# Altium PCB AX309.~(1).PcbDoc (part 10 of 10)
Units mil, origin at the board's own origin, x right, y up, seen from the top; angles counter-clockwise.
Board outline 5185 x 3614 mil, 4 copper layers (Top Layer, GND, Mid-Layer 1, Bottom Layer); 191 components, 352 nets, 1106 pads, 425 vias.
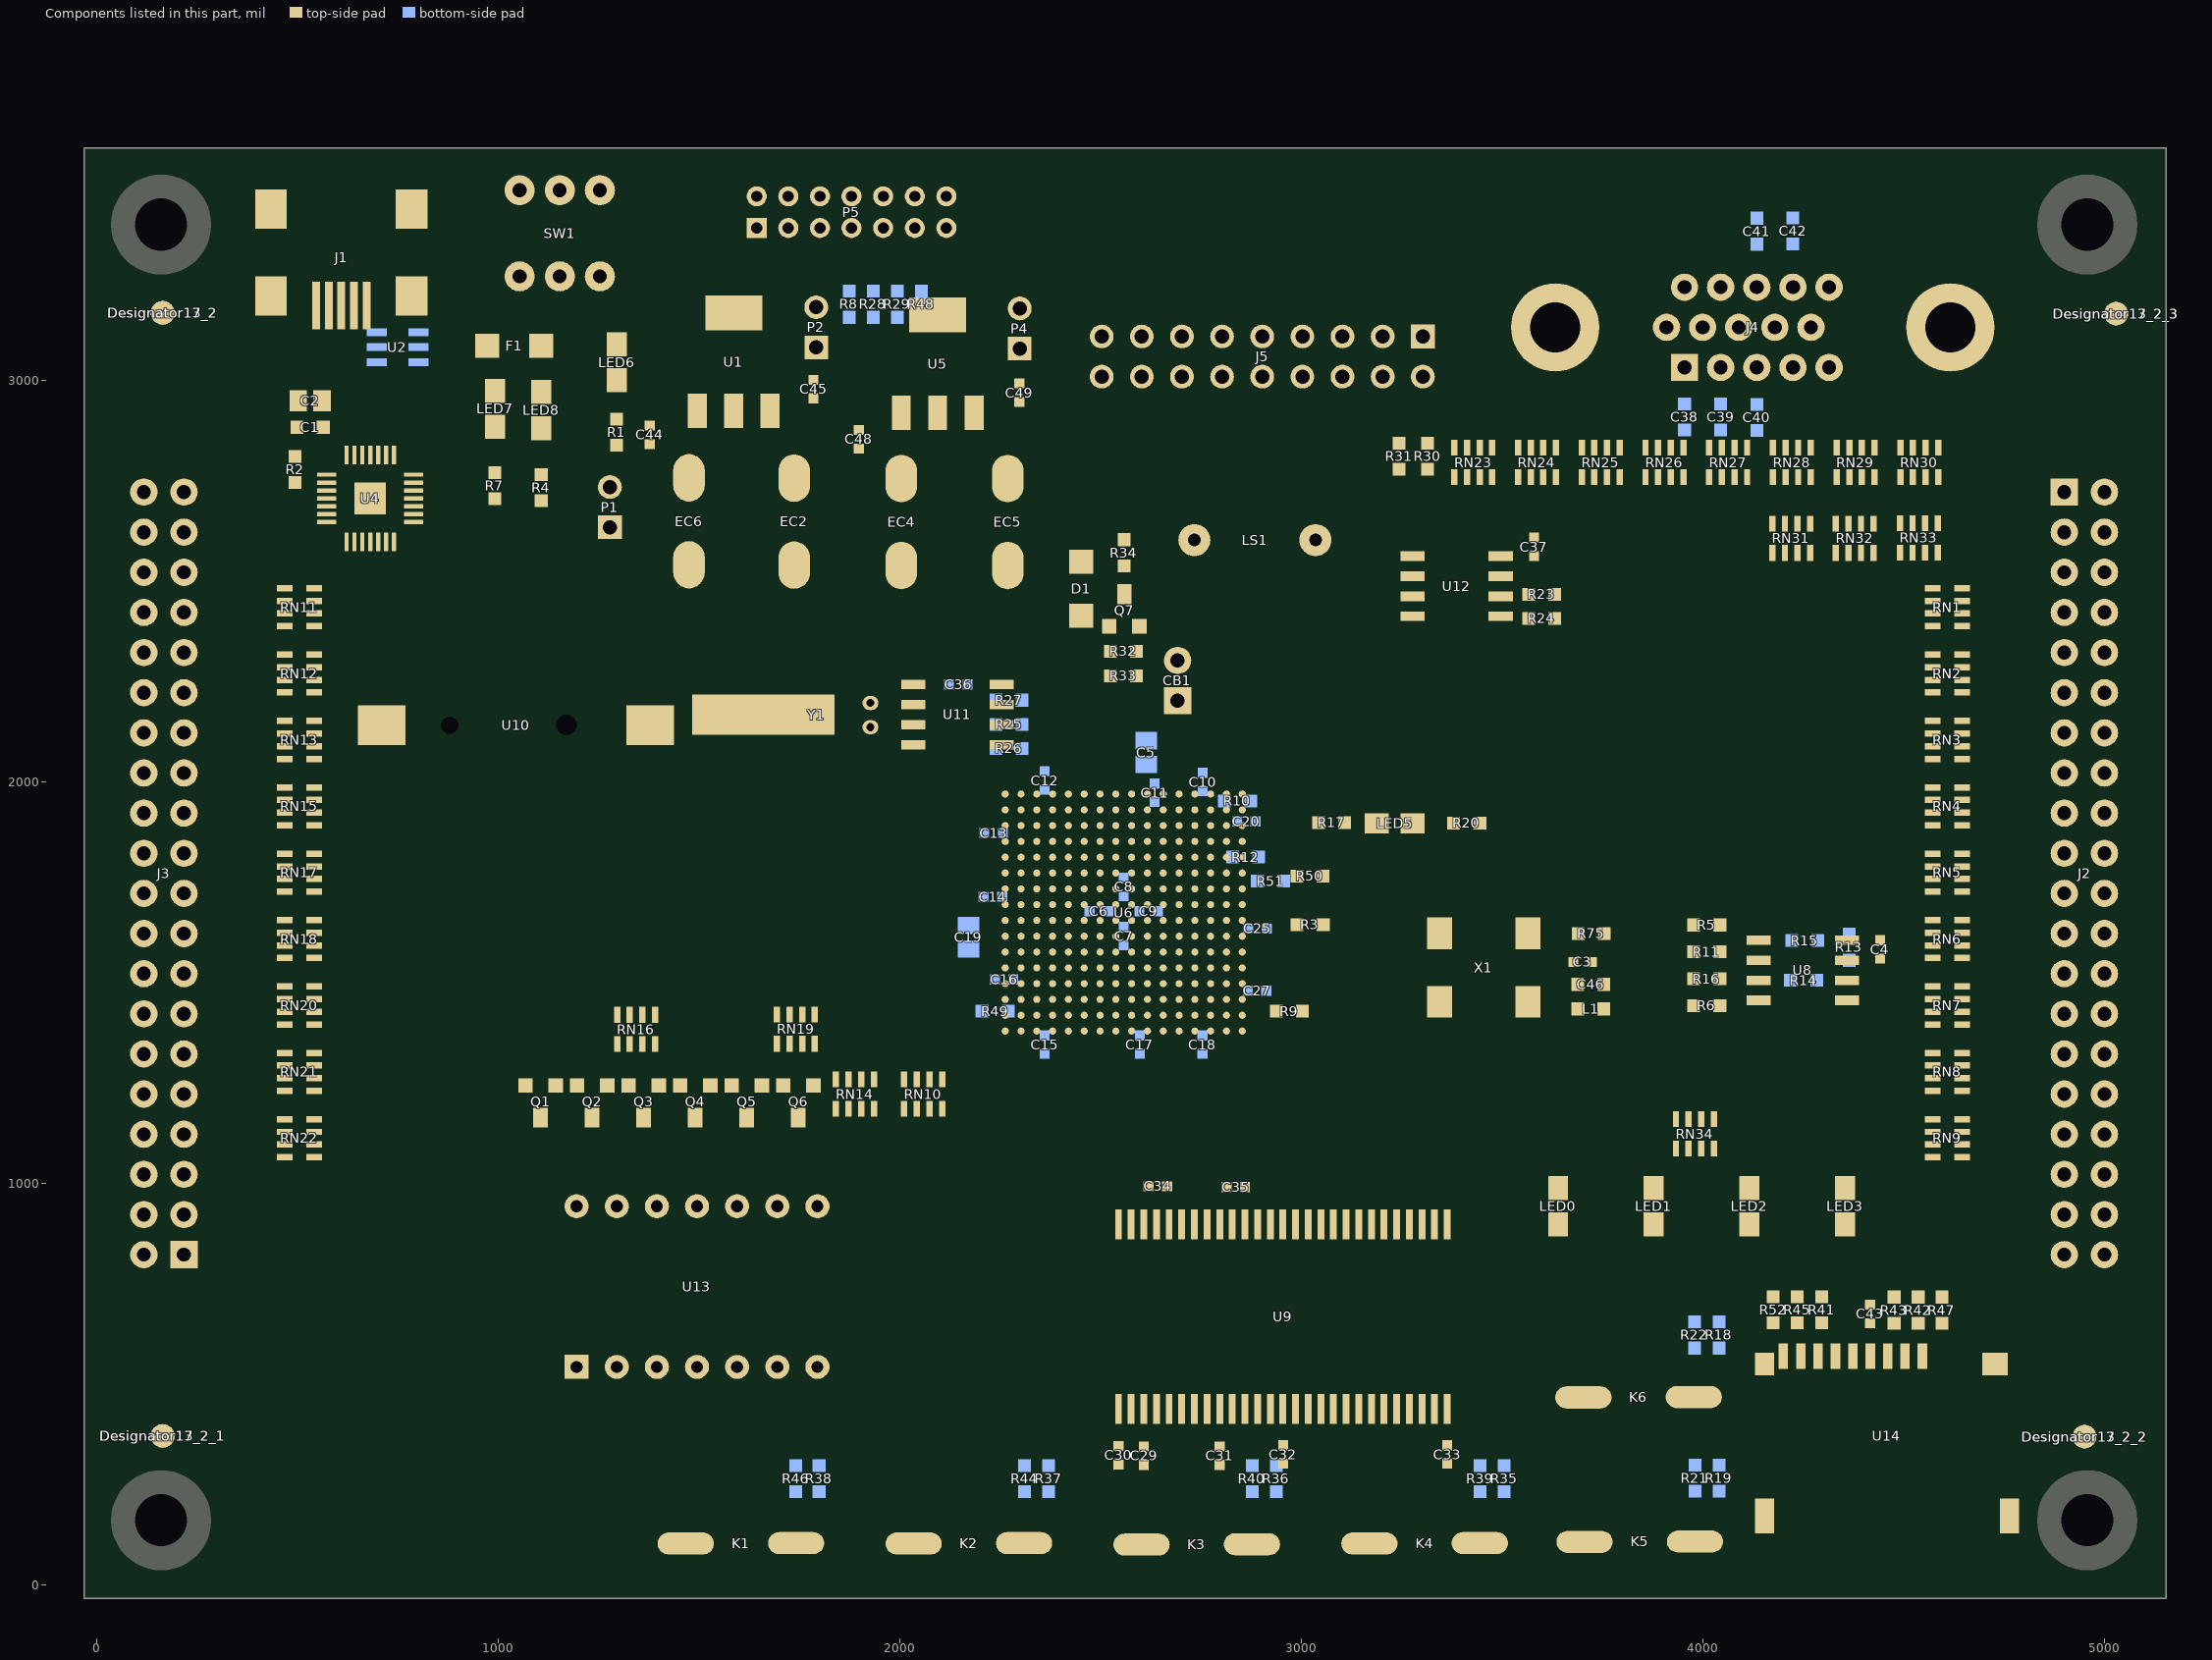
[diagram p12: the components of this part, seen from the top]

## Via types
v1: diameter 20, hole 10, Top Layer to Bottom Layer, 328 vias
v2: diameter 30, hole 15, Top Layer to Bottom Layer, 95 vias
v3: diameter 40, hole 20, Top Layer to Bottom Layer, 2 vias

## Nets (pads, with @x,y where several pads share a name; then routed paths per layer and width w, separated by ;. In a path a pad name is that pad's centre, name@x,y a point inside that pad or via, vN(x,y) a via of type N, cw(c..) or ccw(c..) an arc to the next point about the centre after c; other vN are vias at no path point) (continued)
copper on no net: (continued)
  Top Layer w0.7: 1160.7,143.2 1182.63,143.2 ; 1160.7,183.1 1200.13,183.1 ; 1160.7,183.8 1200.83,183.8 ; 1161.4,143.9 1181.93,143.9 ; 1161.4,181.7 1198.73,181.7 ; 1161.4,182.4 1199.43,182.4 ; 1162.1,144.6 1181.93,144.6 ; 1162.1,180.3 1197.33,180.3 ; 1162.1,181 1198.03,181 ; 1162.8,145.3 1181.23,145.3 ; 1162.8,179.6 1196.63,179.6 ; 1163.5,146 1181.23,146 ; 1163.5,178.2 1195.23,178.2 ; 1163.5,178.9 1195.93,178.9 ; 1164.2,146.7 1180.53,146.7 ; 1164.2,176.8 1193.83,176.8 ; 1164.2,177.5 1194.53,177.5 ; 1164.9,147.4 1180.53,147.4 ; 1164.9,175.4 1192.43,175.4 ; 1164.9,176.1 1193.13,176.1 ; 1165.6,148.1 1179.83,148.1 ; 1165.6,174.7 1191.73,174.7 ; 1166.3,148.8 1179.83,148.8 ; 1166.3,149.5 1179.13,149.5 ; 1166.3,173.3 1190.33,173.3 ; 1166.3,174 1191.03,174 ; 1167,150.2 1179.13,150.2 ; 1167,171.9 1188.93,171.9 ; 1167,172.6 1189.63,172.6 ; 1167.7,150.9 1178.43,150.9 ; 1167.7,170.5 1187.53,170.5 ; 1167.7,171.2 1188.23,171.2 ; 1168.4,151.6 1178.43,151.6 ; 1168.4,169.8 1186.83,169.8 ; 1169.1,152.3 1177.73,152.3 ; 1169.1,168.4 1185.43,168.4 ; 1169.1,169.1 1186.13,169.1 ; 1169.8,153 1177.03,153 ; 1169.8,167 1184.03,167 ; 1169.8,167.7 1184.73,167.7 ; 1170.5,153.7 1177.03,153.7 ; 1170.5,165.6 1182.63,165.6 ; 1170.5,166.3 1183.33,166.3 ; 1171.2,154.4 1176.33,154.4 ; 1171.2,164.9 1181.93,164.9 ; 1171.9,155.1 1176.33,155.1 ; 1171.9,163.5 1180.53,163.5 ; 1171.9,164.2 1181.23,164.2 ; 1172.6,155.8 1175.63,155.8 ; 1172.6,162.1 1179.13,162.1 ; 1172.6,162.8 1179.83,162.8 ; 1173.3,156.5 1175.63,156.5 ; 1173.3,160.7 1177.73,160.7 ; 1173.3,161.4 1178.43,161.4 ; 1174,157.2 1174.93,157.2 ; 1174,157.9 1174.93,157.9 ; 1174,159.3 1176.33,159.3 ; 1174,160 1177.03,160 ; 1174.7,158.6 1175.63,158.6 ; 1190.8,157.9 1259.63,157.9 ; 1191.5,156.5 1258.23,156.5 ; 1191.5,157.2 1258.93,157.2 ; 1191.5,158.6 1260.33,158.6 ; 1192.2,155.1 1257.53,155.1 ; 1192.2,155.8 1257.53,155.8 ; 1192.2,159.3 1261.03,159.3 ; 1192.9,153.7 1256.13,153.7 ; 1192.9,154.4 1256.83,154.4 ; 1192.9,160 1261.73,160 ; 1193.6,152.3 1254.73,152.3 ; 1193.6,153 1255.43,153 ; 1193.6,160.7 1262.43,160.7 ; 1194.3,150.9 1253.33,150.9 ; 1194.3,151.6 1254.03,151.6 ; 1194.3,161.4 1263.13,161.4 ; 1195,149.5 1253.33,149.5 ; 1195,150.2 1252.63,150.2 ; 1195,162.1 1263.83,162.1 ; 1195.7,148.8 1253.33,148.8 ; 1195.7,162.8 1264.53,162.8 ; 1196.4,147.4 1254.03,147.4 ; 1196.4,148.1 1254.03,148.1 ; 1196.4,163.5 1265.23,163.5 ; 1197.1,146 1254.73,146 ; 1197.1,146.7 1254.73,146.7 ; 1197.1,164.2 1265.93,164.2 ; 1197.8,144.6 1255.43,144.6 ; 1197.8,145.3 1255.43,145.3 ; 1197.8,164.9 1265.93,164.9 ; 1198.5,143.2 1256.13,143.2 ; 1198.5,143.9 1256.13,143.9 ; 1198.5,165.6 1266.63,165.6 ; 1199.2,141.8 1257.53,141.8 ; 1199.2,142.5 1256.83,142.5 ; 1199.2,166.3 1267.33,166.3 ; 1199.9,140.4 1258.23,140.4 ; 1199.9,141.1 1257.53,141.1 ; 1199.9,167 1268.03,167 ; 1200.6,139 1258.93,139 ; 1200.6,139.7 1258.23,139.7 ; 1200.6,167.7 1268.73,167.7 ; 1201.3,137.6 1259.63,137.6 ; 1201.3,138.3 1258.93,138.3 ; 1201.3,168.4 1269.43,168.4 ; 1202,136.2 1260.33,136.2 ; 1202,136.9 1259.63,136.9 ; 1202,169.1 1270.13,169.1 ; 1202.7,135.5 1260.33,135.5 ; 1202.7,169.8 1270.83,169.8 ; 1203.4,134.1 1261.03,134.1 ; 1203.4,134.8 1261.03,134.8 ; 1203.4,170.5 1271.53,170.5 ; 1204.1,132.7 1261.73,132.7 ; 1204.1,133.4 1261.73,133.4 ; 1204.1,171.2 1272.23,171.2 ; 1204.8,131.3 1263.13,131.3 ; 1204.8,132 1262.43,132 ; 1204.8,171.9 1272.93,171.9 ; 1205.5,129.9 1263.83,129.9 ; 1205.5,130.6 1263.13,130.6 ; 1205.5,172.6 1273.63,172.6 ; 1206.2,128.5 1264.53,128.5 ; 1206.2,129.2 1263.83,129.2 ; 1206.2,173.3 1274.33,173.3 ; 1206.9,127.1 1265.23,127.1 ; 1206.9,127.8 1264.53,127.8 ; 1206.9,174 1274.33,174 ; 1207.6,125.7 1265.93,125.7 ; 1207.6,126.4 1265.23,126.4 ; 1207.6,174.7 1275.03,174.7 ; 1208.3,124.3 1266.63,124.3 ; 1208.3,125 1265.93,125 ; 1208.3,175.4 1275.73,175.4 ; 1209,122.9 1267.33,122.9 ; 1209,123.6 1266.63,123.6 ; 1209,176.1 1276.43,176.1 ; 1209.7,122.2 1267.33,122.2 ; 1209.7,176.8 1277.13,176.8 ; 1210.4,120.8 1268.73,120.8 ; 1210.4,121.5 1268.03,121.5 ; 1210.4,177.5 1277.83,177.5 ; 1211.1,119.4 1269.43,119.4 ; 1211.1,120.1 1268.73,120.1 ; 1211.1,178.2 1278.53,178.2 ; 1211.8,118 1270.13,118 ; 1211.8,118.7 1269.43,118.7 ; 1211.8,178.9 1279.23,178.9 ; 1212.5,116.6 1270.83,116.6 ; 1212.5,117.3 1270.13,117.3 ; 1212.5,179.6 1279.93,179.6 ; 1213.2,115.2 1271.53,115.2 ; 1213.2,115.9 1270.83,115.9 ; 1213.2,180.3 1280.63,180.3 ; 1213.9,113.8 1272.23,113.8 ; 1213.9,114.5 1271.53,114.5 ; 1213.9,181 1281.33,181 ; 1214.6,112.4 1272.93,112.4 ; 1214.6,113.1 1272.23,113.1 ; 1214.6,181.7 1282.03,181.7 ; 1215.3,111.7 1273.63,111.7 ; 1215.3,182.4 1282.73,182.4 ; 1216,110.3 1274.33,110.3 ; 1216,111 1273.63,111 ; 1216,183.1 1282.73,183.1 ; 1216.7,108.9 1275.03,108.9 ; 1216.7,109.6 1274.33,109.6 ; 1216.7,183.8 1283.43,183.8 ; 1217.4,107.5 1275.73,107.5 ; 1217.4,108.2 1275.03,108.2 ; 1217.4,184.5 1284.13,184.5 ; 1218.1,106.8 1275.73,106.8 ; 1218.1,185.2 1284.83,185.2 ; 1218.8,105.4 1276.43,105.4 ; 1218.8,106.1 1276.43,106.1 ; 1218.8,185.9 1285.53,185.9 ; 1219.5,104 1277.13,104 ; 1219.5,104.7 1277.13,104.7 ; 1219.5,186.6 1286.23,186.6 ; 1220.2,102.6 1277.83,102.6 ; 1220.2,103.3 1277.83,103.3 ; 1220.2,187.3 1286.93,187.3 ; 1220.9,101.2 1279.23,101.2 ; 1220.9,101.9 1278.53,101.9 ; 1220.9,188 1287.63,188 ; 1221.6,99.8 1279.93,99.8 ; 1221.6,100.5 1279.23,100.5 ; 1221.6,188.7 1288.33,188.7 ; 1222.3,98.4 1280.63,98.4 ; 1222.3,99.1 1279.93,99.1 ; 1222.3,189.4 1289.03,189.4 ; 1223,97 1281.33,97 ; 1223,97.7 1280.63,97.7 ; 1223,190.1 1289.73,190.1 ; 1223.7,95.6 1282.03,95.6 ; 1223.7,96.3 1281.33,96.3 ; 1223.7,190.8 1290.43,190.8 ; 1224.4,94.2 1282.73,94.2 ; 1224.4,94.9 1282.03,94.9 ; 1224.4,191.5 1291.13,191.5 ; 1225.1,92.8 1283.43,92.8 ; 1225.1,93.5 1282.73,93.5 ; 1225.1,192.2 1291.83,192.2 ; 1225.8,91.4 1284.13,91.4 ; 1225.8,92.1 1284.13,92.1 ; 1225.8,192.9 1291.83,192.9 ; 1226.5,90 1284.83,90 ; 1226.5,90.7 1284.83,90.7 ; 1226.5,193.6 1292.53,193.6 ; 1227.2,89.3 1285.53,89.3 ; 1227.2,194.3 1293.23,194.3 ; 1227.9,87.9 1286.23,87.9 ; 1227.9,88.6 1285.53,88.6 ; 1227.9,195 1293.93,195 ; 1228.6,86.5 1286.93,86.5 ; 1228.6,87.2 1286.23,87.2 ; 1228.6,195.7 1294.63,195.7 ; 1229.3,85.1 1287.63,85.1 ; 1229.3,85.8 1286.93,85.8 ; 1229.3,196.4 1295.33,196.4 ; 1230,83.7 1288.33,83.7 ; 1230,84.4 1287.63,84.4 ; 1230,197.1 1296.03,197.1 ; 1230,197.8 1296.73,197.8 ; 1230.7,82.3 1289.03,82.3 ; 1230.7,83 1288.33,83 ; 1230.7,198.5 1297.43,198.5 ; 1231.4,80.9 1289.73,80.9 ; 1231.4,81.6 1289.73,81.6 ; 1231.4,199.2 1298.13,199.2 ; 1232.1,79.5 1290.43,79.5 ; 1232.1,80.2 1290.43,80.2 ; 1232.1,199.9 1298.83,199.9 ; 1232.8,78.1 1291.13,78.1 ; 1232.8,78.8 1291.13,78.8 ; 1232.8,200.6 1299.53,200.6 ; 1233.5,76.7 1291.83,76.7 ; 1233.5,77.4 1291.83,77.4 ; 1233.5,201.3 1300.23,201.3 ; 1234.2,75.3 1292.53,75.3 ; 1234.2,76 1292.53,76 ; 1234.2,202 1300.23,202 ; 1234.9,73.9 1293.23,73.9 ; 1234.9,74.6 1293.23,74.6 ; 1234.9,202.7 1300.93,202.7 ; 1235.6,72.5 1294.63,72.5 ; 1235.6,73.2 1293.93,73.2 ; 1235.6,203.4 1301.63,203.4 ; 1235.6,204.1 1302.33,204.1 ; 1236.3,71.1 1295.33,71.1 ; 1236.3,71.8 1294.63,71.8 ; 1236.3,204.8 1303.03,204.8 ; 1237,70.4 1295.33,70.4 ; 1237,205.5 1303.73,205.5 ; 1237.7,69 1296.03,69 ; 1237.7,69.7 1296.03,69.7 ; 1237.7,206.2 1304.43,206.2 ; 1238.4,67.6 1296.73,67.6 ; 1238.4,68.3 1296.73,68.3 ; 1238.4,206.9 1305.13,206.9 ; 1239.1,66.2 1297.43,66.2 ; 1239.1,66.9 1297.43,66.9 ; 1239.1,207.6 1305.83,207.6 ; 1239.8,64.8 1298.13,64.8 ; 1239.8,65.5 1298.13,65.5 ; 1239.8,208.3 1306.53,208.3 ; 1240.5,63.4 1298.83,63.4 ; 1240.5,64.1 1298.83,64.1 ; 1240.5,209 1307.23,209 ; 1240.5,209.7 1307.93,209.7 ; 1241.2,62 1300.23,62 ; 1241.2,62.7 1299.53,62.7 ; 1241.2,210.4 1308.63,210.4 ; 1241.9,60.6 1300.93,60.6 ; 1241.9,61.3 1300.23,61.3 ; 1241.9,211.1 1308.63,211.1 ; 1242.6,59.9 1300.93,59.9 ; 1242.6,211.8 1309.33,211.8 ; 1243.3,212.5 1310.03,212.5 ; 1244,213.2 1310.73,213.2 ; 1244.7,213.9 1311.43,213.9 ; 1245.4,214.6 1312.13,214.6 ; 1245.4,215.3 1312.83,215.3 ; 1246.1,216 1313.53,216 ; 1246.8,216.7 1314.23,216.7 ; 1247.5,217.4 1314.93,217.4 ; 1248.2,218.1 1315.63,218.1 ; 1248.9,218.8 1316.33,218.8 ; 1249.6,219.5 1317.03,219.5 ; 1250.3,220.2 1317.03,220.2 ; 1250.3,220.9 1317.73,220.9 ; 1251,221.6 1318.43,221.6 ; 1251.7,222.3 1319.13,222.3 ; 1252.4,223 1319.83,223 ; 1253.1,223.7 1320.53,223.7 ; 1253.8,224.4 1321.23,224.4 ; 1254.5,225.1 1321.93,225.1 ; 1255.2,225.8 1322.63,225.8 ; 1255.2,226.5 1323.33,226.5 ; 1255.9,227.2 1324.03,227.2 ; 1256.6,227.9 1324.73,227.9 ; 1257.3,228.6 1325.43,228.6 ; 1258,229.3 1325.43,229.3 ; 1258.7,230 1326.13,230 ; 1259.4,230.7 1326.83,230.7 ; 1260.1,231.4 1327.53,231.4 ; 1260.8,232.1 1328.23,232.1 ; 1260.8,232.8 1328.93,232.8 ; 1261.5,233.5 1329.63,233.5 ; 1262.2,234.2 1330.33,234.2 ; 1262.9,234.9 1331.03,234.9 ; 1263.6,235.6 1331.73,235.6 ; 1264.3,236.3 1332.43,236.3 ; 1265,237 1333.13,237 ; 1265.7,237.7 1333.83,237.7 ; 1265.7,238.4 1333.83,238.4 ; 1266.4,239.1 1334.53,239.1 ; 1267.1,239.8 1335.23,239.8 ; 1267.8,240.5 1335.93,240.5 ; 1268.5,241.2 1336.63,241.2 ; 1269.2,241.9 1337.33,241.9 ; 1269.9,242.6 1338.03,242.6 ; 1270.6,243.3 1338.73,243.3 ; 1270.6,244 1339.43,244 ; 1271.3,244.7 1340.13,244.7 ; 1272,245.4 1340.83,245.4

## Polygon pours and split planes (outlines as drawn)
D1V2 on Mid-Layer 1 "Bottom Layer-No Net" (solid, pour order 2): 2453,1779 2660.95,1779 2662,1779 2662,1568 2454.05,1568 2453,1568 2453,1779
D3V3 on Bottom Layer "Bottom Layer-No Net" (solid, remove dead copper, pour order 3): 2300,1963 2915,1963 2915,1807 2915,1382 2747,1382 2300,1382 2300,1963
GND on Bottom Layer "Bottom Layer-No Net" (hatched 45Degree grid 20 track 8, remove dead copper, pour order 6): 120.71,3543.01 5118.11,3543.01 5118.11,3388 5118.11,0 4969,0 0,0 0,297 0,3543.31 121.01,3543.31
GND on GND (split plane): 5133.9,3242.3 5133.9,-14.6 -10.9,-14.6 -10.9,3559.2 5133.9,3559.2

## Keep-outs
Keep-Out Layer:
  lines w8: 0,121.01 0,3422.3 cw(c120.71,3422.3) 120.71,3543.01 ; 0.29,121.01 ccw(c121,121.01) 121,0.3 ; 117,0 4997.29,0 ccw(c4997.3,120.71) 5118.01,120.71 ; 121.01,3543.31 4997.29,3543.31 ; 4997.29,3543.01 cw(c4997.29,3422.3) 5118,3422.3 ; 5118.11,117.3 5118.11,3422.3

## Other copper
Top Layer:
  rectangle net VCC: 1219,3228 1579,3512
  rectangle net D3V3: 2398,207 2454,440
  rectangle net D3V3: 3821,1431 3878,1487
  rectangle net NetC3_1: 3533,1412 3691,1543
  rectangle net VBUS: 662,3066 733,3246
  rectangle net GND: 482,3049 556,3245
  rectangle net NetF1_2: 1111,3068 1196,3514
  rectangle net VBUS: 662,3056 1002,3116
  rectangle net D3V3: 1563,2697 1611,3182
  rectangle net D3V3: 1241,2697 1611,2854
  rectangle net VCC: 1654,2695 1806,2969
  rectangle net D1V2: 2072,2690 2119,3206
  rectangle net D1V2: 1885,2690 2119,2844
  rectangle net D3V3: 2162,2686 2314,2963
  rectangle net GND: 1364,2874 1520,3085
  rectangle net GND: 1885,2863 2028,2963
  rectangle net GND: 1246,2474 2316,2607
  rectangle net GND: 4130,130 4179,310
  rectangle net GND: 4741,127 4788,311
  rectangle net GND: 4697,438 4761,576
  rectangle net D1V2: 2023,3120 2333,3213
  rectangle net VCC: 551,2791 627,2840
  rectangle net GND: 651,2092 768,2287
  rectangle net VCC: 549,2759 597,2840
  rectangle net NetF1_2: 1077,3053 1196,3107
  rectangle net GND: 3313,1583 3420,1662
  rectangle net GND: 1249,2482 1307,2661
Mid-Layer 1:
  rectangle net D3V3: 3818,1358 3877,1487
  rectangle net D1V2: 1894,2679 2579,2857
  rectangle net D1V2: 2537,1735 2579,2833
  rectangle net D3V3: 1237,2694 1612,2863
Bottom Layer:
  rectangle net GND: 4843,874 5059,970
  rectangle net GND: 4853,2669 4951,2769.65
  rectangle net GND: 3858,3084.73 4129.65,3176
  rectangle net GND: 54,2576 274,2670
  rectangle net GND: 169,773.65 265,871.65
  rectangle net D3V3: 2654,1535 2697,1577
  rectangle net D3V3: 2575.5,1740 2620,1778.5
  rectangle net D3V3: 2215,2867 2316,2962
  rectangle net D3V3: 1242,2694 1613,3026
  rectangle net D3V3: 2419,1768.03 2463,1814
  rectangle net D3V3: 1418,1652 1507,2767
  rectangle net D3V3: 1418,1619 2317,1689
  rectangle net D3V3: 2260,1465.86 2305.5,1576
  rectangle net D3V3: 2810,1468 2846,1505
  rectangle net D3V3: 2812,1842.3 2846,1923.5
  rectangle net D3V3: 2613,1847 2659,1892
  rectangle net D3V3: 2862,1782 2915,1851.17
  rectangle net D3V3: 2245,1858 2304,1885
  rectangle net D3V3: 2455,1733 2501,1776
  rectangle net D3V3: 2243,1682 2303,1726

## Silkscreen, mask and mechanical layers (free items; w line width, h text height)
Top Overlay:
  drawing of 6031 lines, arcs and shapes, not listed
  text "PWR" at 895,3362 h80 r90
  text "VGA" at 3482,3361 h80 r90
  text "5V" at 1899,3159 h60 r90
  text "1.2V" at 2413,3141 h60 r90
  text "【39】" at 193,3112 h80 r270
  text "【40】" at 80,3111 h80 r270
  text "PWR" at 1235,3021 h60 r90
  text "GND" at 1899,2992 h60 r90
  text "GND" at 2415,2985 h60 r90
  text "【1】" at 4924,2964 h80 r90
  text "【2】" at 5031,2964 h80 r90
  text "CAMERA" at 2759,2867 h80
  text "3.3V" at 1201,2709 h60 r90
  text "IO: 3.3V" at 4769,2574 h100 r90
  text "GND" at 1201,2545 h60 r90
  text "IO: 3.3V" at 352,944 h100 r270
  text "【2】" at 93,573 h80 r270
  text "【1】" at 193,573 h80 r270
  text "【39】" at 4924,438 h80 r90
  text "【40】" at 5037,435 h80 r90
Bottom Overlay:
  lines w8: 301.61,1567.33 660,1567.33 ; 302,1067.33 660,1067.33 ; 302,1267.33 660,1267.33 ; 302.31,2167.33 657,2167.33 ; 302.62,1367.33 660,1367.33 ; 303,867.33 660,867.33 660,969.33 303,969.33 ; 303,1167.33 659,1167.33 ; 303,1467.33 659.16,1467.33 ; 303,1666.33 660,1666.33 ; 303,1767.33 659,1767.33 ; 303,1867.33 657,1867.33 ; 303,1967.33 659,1967.33 ; 303,2068.33 656.86,2068.33 ; 303,2267.33 656.87,2267.33 ; 303,2367.33 657,2367.33 ; 303,2467.33 659,2467.33 ; 303,2570.33 658,2570.33 ; 303,2667.33 657,2667.33 ; 478,767.68 479,767.68 479,2770.33 ; 4471,1871.67 4828,1871.67 ; 4471,1970.67 4829.39,1970.67 ; 4471,2170.67 4828.38,2170.67 ; 4471,2270.67 4829,2270.67 ; 4471,2470.67 4829,2470.67 ; 4471.84,2070.67 4828,2070.67 ; 4472,1070.67 4828,1070.67 ; 4472,1570.67 4828,1570.67 ; 4472,1770.67 4828,1770.67 ; 4472,2370.67 4828,2370.67 ; 4473,967.67 4828,967.67 ; 4474,870.67 4828,870.67 ; 4474,1170.67 4828,1170.67 ; 4474,1370.67 4828.69,1370.67 ; 4474,1670.67 4828,1670.67 ; 4474.13,1270.67 4828,1270.67 ; 4474.14,1469.67 4828,1469.67 ; 4652,767.67 4652,2770.32 4653,2770.32 ; 4828,2568.67 4471,2568.67 4471,2670.67 4828,2670.67
  lines w12: 303,2770.33 303,767.33 660,767.33 660,2772.33 303,2772.33 ; 4828,765.67 4471,765.67 4471,2770.67 4828,2770.67 4828,767.67
  text "【1】" at 4618,2806 h80
  text "【2】" at 4793,2804.38 h80
  text "3V3" at 647,2695 h80
  text "GND" at 4634,2694.67 h80
  text "3V3" at 468,2693 h80
  text "VCC" at 4815,2691.91 h80
  text "K16" at 4634,2594 h80
  text "J16" at 4815,2594 h80
  text "GND" at 468,2592 h80
  text "GND" at 647,2592 h80
  text "H16" at 468,2494 h80
  text "K15" at 4815,2494 h80
  text "L16" at 4634,2493 h80
  text "H15" at 647,2491 h80
  text "M15" at 4634,2397 h80
  text "M16" at 4815,2395 h80
  text "G16" at 468,2392 h80
  text "F16" at 647,2392 h80
  text "E16" at 647,2294 h80
  text "N16" at 4815,2293 h80
  text "F15" at 468,2292 h80
  text "P16" at 4634,2292 h80
  text "R16" at 4634,2195.67 h80
  text "P15" at 4815,2192.67 h80
  text "D11" at 468,2191 h80
  text "C10" at 647,2191 h80
  text "T15" at 4634,2095 h80
  text "C9" at 647,2093 h80
  text "R15" at 4815,2093.67 h80
  text "E11" at 468,2092 h80
  text "T14" at 4634,1995 h80
  text "E15" at 468,1993 h80
  text "R14" at 4815,1992.67 h80
  text "D16" at 647,1991 h80
  text "R12" at 4634,1895 h80
  text "C16" at 468,1894 h80
  text "T13" at 4815,1893 h80
  text "C15" at 647,1892 h80
  text "T12" at 4815,1794 h80
  text "R9" at 4634,1793 h80
  text "B16" at 468,1792 h80
  text "B15" at 647,1792 h80
  text "L8" at 4634,1695 h80
  text "T9" at 4815,1694 h80
  text "B14" at 468,1692 h80
  text "A14" at 647,1692 h80
  text "T7" at 4815,1596 h80
  text "R7" at 4634,1593 h80
  text "A13" at 468,1592.13 h80
  text "B12" at 647,1592.13 h80
  text "T5" at 4634,1495 h80
  text "A11" at 647,1494 h80
  text "T6" at 4815,1494 h80
  text "A12" at 468,1492 h80
  text "T4" at 4634,1396 h80
  text "R5" at 4815,1394 h80
  text "B10" at 468,1391.82 h80
  text "A10" at 647,1391 h80
  text "R2" at 4634,1294 h80
  text "R1" at 4815,1293 h80
  text "A9" at 468,1292 h80
  text "C8" at 647,1288 h80
  text "P2" at 4634,1196 h80
  text "M4" at 4815,1193 h80
  text "A8" at 468,1192 h80
  text "B8" at 647,1192 h80
  text "P6" at 4634,1096 h80
  text "N6" at 4815,1093 h80
  text "A7" at 468,1090 h80
  text "A6" at 647,1090 h80
  text "A5" at 647,994 h80
  text "M5" at 4634,993 h80
  text "N4" at 4815,992 h80
  text "B6" at 468,991 h80
  text "B5" at 468,893 h80
  text "A4" at 647,892 h80
  text "GND" at 4634,890.67 h80
  text "GND" at 4815,890.67 h80
  text "VCC" at 468,793 h80
  text "GND" at 647,793 h80
  text "3V3" at 4634,792.67 h80
  text "3V3" at 4815,790.67 h80
  text "【2】" at 450,681 h80
  text "【1】" at 629,678 h80
  text "AX309" at 1136,55 h200
Top Solder:
  rectangle: 313,35 1351,272
Mechanical 4:
  circle w10: c160,160 r64.41
  circle w10: c160,3388 r65.12
  circle w10: c4958.11,3388 r64.8
  circle w10: c4958.11,160 r64.22
  lines w8: 0,3422 0,3178 ccw(c28.39,3178) 28.39,3149.61 368,3149.61 368,393.7 29,393.7 ccw(c29,364.99) 0.29,364.99 ; 0,3422.6 cw(c120.71,3422.6) 120.71,3543.31 ; 0.29,120.71 0.29,364.99 ; 0.29,121.31 ccw(c121,121.31) 121,0.6 ; 0.29,363 0.29,364.99 ; 120.71,3542.71 955.45,3542.71 ; 121,0 1315,0 ccw(c1315,27) 1342,27 1342,28 ; 953,3542.71 955.45,3542.71 ; 1320.81,3200.95 2389,3200.95 2389,3505 2389,3517.31 cw(c2415,3517.31) 2415,3543.31 4997.29,3543.31 cw(c4997.29,3422.6) 5118,3422.6 ; 1321,3200.95 986.16,3200.95 986.16,3512 ccw(c955.45,3512) 955.45,3542.71 ; 1342.24,27.24 1342.24,256 4114,256 4114,26 ccw(c4140,26) 4140,0 4997.3,0 ; 4997.3,0.3 ccw(c4997.3,121.01) 5118.01,121.01 ; 5118.01,120.41 5118.01,365.9 5118.11,366 ; 5118,3422 5118.11,3422 5118.11,3178.72 ; 5118.11,367.7 ccw(c5092.11,367.7) 5092.11,393.7 4745,393.7 4745,3149.61 5089,3149.61 ccw(c5089,3178.72) 5118.11,3178.72 ; 5118.11,3203 5118.11,3178.72

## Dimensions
121.01,3543.31 to 117,0 on Drill Drawing
0,121.01 to 5118.11,117.3 on Drill Drawing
